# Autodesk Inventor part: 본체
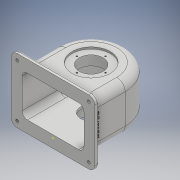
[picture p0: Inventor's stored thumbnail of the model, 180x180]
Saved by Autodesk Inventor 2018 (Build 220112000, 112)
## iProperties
Created: 2022-09
Part Number: 본체
Material: 일반
Document SubType Name: Modeling
Designer: home
Density: 1 g/cm^3
Appearance: 기본값
Mass: 792.206 g
Surface Area: 1125.07 cm^2
Volume: 293.41 cm^3
Author: home
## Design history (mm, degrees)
sketch "스케치1"
  geometry: L1 (-57, 0)-(-57, -64); L2 (57, 0)-(57, -64); L3 (57, -64)-(-57, -64); A1 r 57 centre (0, 0) between (57, 0) and (-57, 0); 1 further point
  constraints: 6 end point, 2 point on circle, 2 vertical, 1 centre point, 1 coincident, 1 perpendicular
  dimensions: "d0" = 57 radius of A1; "d1" = 64 distance of L1.start L1.end; "d2" = 64 distance of L2.start L2.end
extrude "돌출1" new body sketch "스케치1" distance "d3" = 78; taper "d4" = 0 deg
sketch "스케치2"
  geometry: L1 (0, 0)-(0, 78) reference; L2 (0, 78)-(114, 78) reference; L3 (114, 78)-(114, 0) reference; L4 (114, 0)-(0, 0) reference; L5 (-13, 93)-(127, 93); L6 (127, 93)-(127, -15); L7 (127, -15)-(-13, -15); L8 (-13, -15)-(-13, 93); L9 (-13, 93)-(127, -15); L10 (127, 93)-(-13, -15); L11 (0, 0)-(0, 78) reference; L12 (0, 78)-(114, 78) reference; L13 (114, 78)-(114, 0) reference; L14 (114, 0)-(0, 0) reference; 2 further points
  constraints: 12 end point, 2 midpoint, 2 parallel, 1 horizontal, 1 perpendicular
  dimensions: "d5" = 140 distance of L6.end L7.end; "d6" = 108 distance of L5.end L6.end
  node "절단 모서리 투영1"
  node "절단 모서리 투영6"
feature "쉘1" dims "d7" = 5
extrude "돌출2" join sketch "스케치2" distance "d8" = 7; taper "d9" = 0 deg
fillet "모깎기1" dims "d12" = 14
fillet "모깎기2" dims "d13" = 10
sketch "스케치5"
  geometry: L1 (43, -57)-(43, 0) reference; L2 (-43, 0)-(-43, -57) reference; L3 (-70, -57)-(-43, -57) reference; L4 (43, -57)-(70, -57) reference; L5 (-43, -57)-(43, -57) reference; L6 (-70, -64)-(-70, -57) reference; L7 (70, -64)-(-70, -64) reference; L8 (70, -57)-(70, -64) reference; A1 r 43 centre (0, 0) between (43, 0) and (-43, 0) reference; 1 further point
  node "절단 모서리 투영4"
sketch "스케치8"
  geometry: 1 further point
hole "구멍2" diameter "d28" = 40; stored, may be unused: countersink angle "d32" = 90 deg, drill point angle "d34" = 0 deg; dims "d29" = 12, "d30" = 64, "d31" = 3, "d33" = 20, "d132" = 10, "d133" = 10
sketch "스케치9" dims "d37" = 24
  geometry: 3 further points
  constraints: 1 coincident, 1 vertical alignment, 2 other
hole "구멍3" sketch "스케치9" at (0, 24) diameter "d38" = 2.459; stored, may be unused: countersink angle "d42" = 90 deg, drill point angle "d44" = 0 deg; dims "d39" = 7, "d40" = 4, "d41" = 2, "d43" = 9
sketch "스케치10"
  geometry: C1 r 20 at (0, 0) reference; C2 r 31 at (0, 0); 1 further point
  constraints: 1 centre point, 1 coincident
  dimensions: "d48" = 31 radius of C2
extrude "돌출5" join sketch "스케치10" distance "d49" = 15; taper "d50" = 0 deg
hole "구멍4" diameter "d53" = 35; stored, may be unused: countersink angle "d57" = 90 deg, drill point angle "d59" = 0 deg; dims "d54" = 7, "d55" = 40, "d56" = 16, "d58" = 9, "d172" = 10, "d173" = 10
fillet "모깎기3" dims "d60" = 0.6
sketch "스케치12"
  geometry: 1 further point
node "작업 평면3"
sketch "스케치13"
  geometry: 1 further point
sketch "스케치14"
  geometry: 1 further point
sketch "스케치15"
  geometry: L1 (17, 93)-(103, 93) reference; L2 (60, 93)-(60, 54); C1 r 6 at (60, 54); 1 further point
  constraints: 2 end point, 1 centre point, 1 coincident, 1 midpoint, 1 vertical
  dimensions: "d75" = 39 distance of L2.start L2.end; "d76" = 6 radius of C1
extrude "돌출6" join sketch "스케치15" stored distance "d77" = 15; taper "d78" = 0 deg
hole "구멍6" diameter "d81" = 4.917; stored, may be unused: countersink angle "d85" = 90 deg, drill point angle "d87" = 0 deg; dims "d79" = 10, "d80" = 10, "d82" = 12, "d83" = 4, "d84" = 2, "d86" = 17.1
hole "구멍7" diameter "d90" = 4.917; stored, may be unused: countersink angle "d94" = 90 deg, drill point angle "d96" = 0 deg; dims "d88" = 10, "d89" = 10, "d91" = 12, "d92" = 4, "d93" = 2, "d95" = 17.1
hole "구멍8" diameter "d99" = 4.917; stored, may be unused: countersink angle "d103" = 90 deg, drill point angle "d105" = 0 deg; dims "d97" = 10, "d98" = 10, "d100" = 12, "d101" = 4, "d102" = 2, "d104" = 17.1
hole "구멍9" diameter "d108" = 4.917; stored, may be unused: countersink angle "d112" = 90 deg, drill point angle "d114" = 0 deg; dims "d106" = 10, "d107" = 10, "d109" = 12, "d110" = 4, "d111" = 2, "d113" = 17.1
fillet "모깎기5" dims "d115" = 3
hole "구멍10" diameter "d118" = 5.188; stored, may be unused: countersink angle "d122" = 90 deg, drill point angle "d124" = 0 deg; dims "d116" = 10, "d117" = 10, "d119" = 29, "d120" = 4, "d121" = 2, "d123" = 30
fillet "모깎기6" dims "d125" = 3
node "작업 평면4"
sketch "스케치16"
  geometry: C1 r 28 at (0, 0); 1 further point
  constraints: 1 centre point, 1 coincident
  dimensions: "d127" = 28 radius of C1
extrude "돌출7" join sketch "스케치16" distance "d128" = 15; taper "d129" = 30 deg
hole "구멍11" diameter "d134" = 40; stored, may be unused: countersink angle "d138" = 90 deg, drill point angle "d140" = 0 deg; dims "d130" = 10, "d131" = 10, "d135" = 29, "d136" = 4, "d137" = 2, "d139" = 20
hole "구멍12" diameter "d143" = 2.459; stored, may be unused: countersink angle "d147" = 90 deg, drill point angle "d149" = 0 deg; dims "d141" = 10, "d142" = 10, "d144" = 7, "d145" = 4, "d146" = 2, "d148" = 9
sketch "스케치17"
  geometry: L1 (50, -54)-(0, -54) reference; L2 (59.644, -57)-(76, -57) reference; L3 (79, -60)-(79, -64) reference; L4 (79, -64)-(-29, -64) reference; L5 (-29, -64)-(-29, -60) reference; L6 (-26, -57)-(-9.644, -57) reference; L7 (0, -54)-(0, 0) reference; L8 (50, 0)-(0, 0) reference; L9 (50, 0)-(50, -54) reference; L10 (-29, -64)-(-29, -47); L11 (-14, 0)-(-14, -54) reference; L12 (-14, -47)-(-14, -8); L13 (-14, -47)-(25, -47); A1 r 3 centre (76, -60) between (79, -60) and (76, -57) reference; A2 r 3 centre (-26, -60) between (-26, -57) and (-29, -60) reference; 2 further points
  constraints: 6 end point, 2 point on line, 1 horizontal, 1 vertical, 3 other
  dimensions: "d153" = 17 distance of L4.end L10.end; "d154" = 39 distance of L12.start L12.end; "d155" = 39 distance of L12.start L13.end
feature "엠보싱1" sketch "스케치17" dims "d12" = 14, "d156" = 0.5, "d157" = 0
fillet "모깎기7" dims "d158" = 3
fillet "모깎기8" dims "d159" = 9
fillet "모깎기9" dims "d160" = 9
sketch "스케치18"
  geometry: C1 r 24 at (0, 0); C2 r 1.23 at (0, 24) reference; 2 further points
  constraints: 2 coincident, 1 centre point
  dimensions: "d161" = 24 radius of C1
hole "구멍13" sketch "스케치18" at (0, 24) diameter "d162" = 2.459; stored, may be unused: countersink angle "d166" = 90 deg, drill point angle "d168" = 118 deg; dims "d163" = 7, "d164" = 4, "d165" = 2, "d167" = 9
fillet "모깎기10" dims "d174" = 1
chamfer "모따기1" distance "d175" = 1; stored, may be unused: second distance "d176" = 2, angle "d177" = 45 deg
node "솔리드1"
pattern_circular "원형 패턴1" dims angle "d46" = 360 deg
pattern_circular "원형 패턴3" dims angle "d151" = 360 deg
pattern_circular "원형 패턴4" dims angle "d170" = 360 deg
node "절단 모서리 투영5"
other parameters: "d74" = -124, "d126" = 14
